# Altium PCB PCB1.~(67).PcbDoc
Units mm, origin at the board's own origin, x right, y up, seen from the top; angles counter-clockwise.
Board outline 68 x 68 mm, 2 copper layers (Top Layer, Bottom Layer); 37 components, 24 nets, 122 pads, 15 vias.
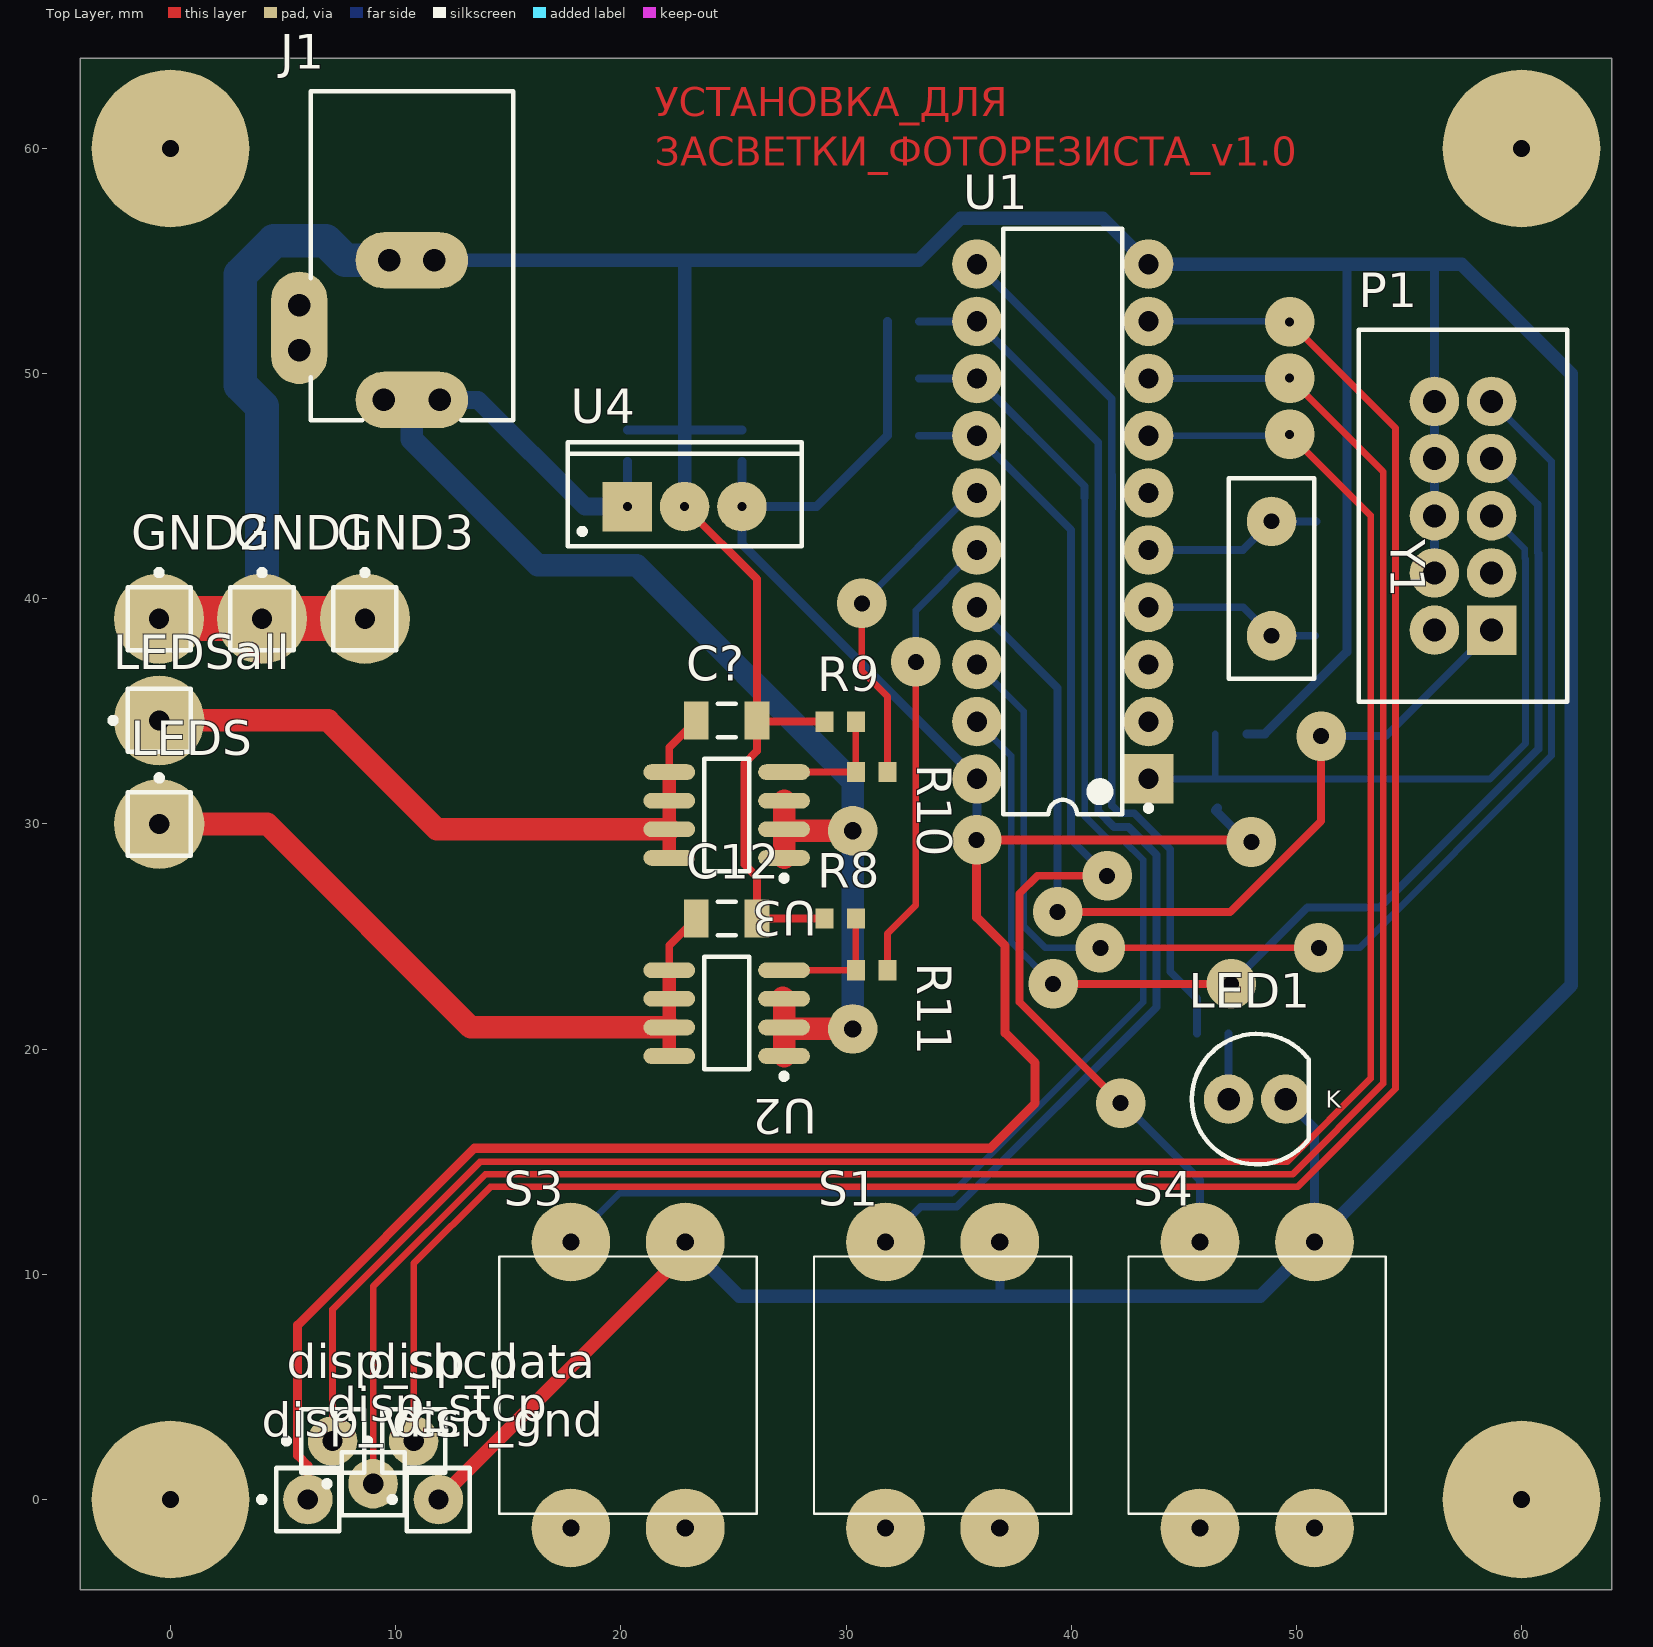
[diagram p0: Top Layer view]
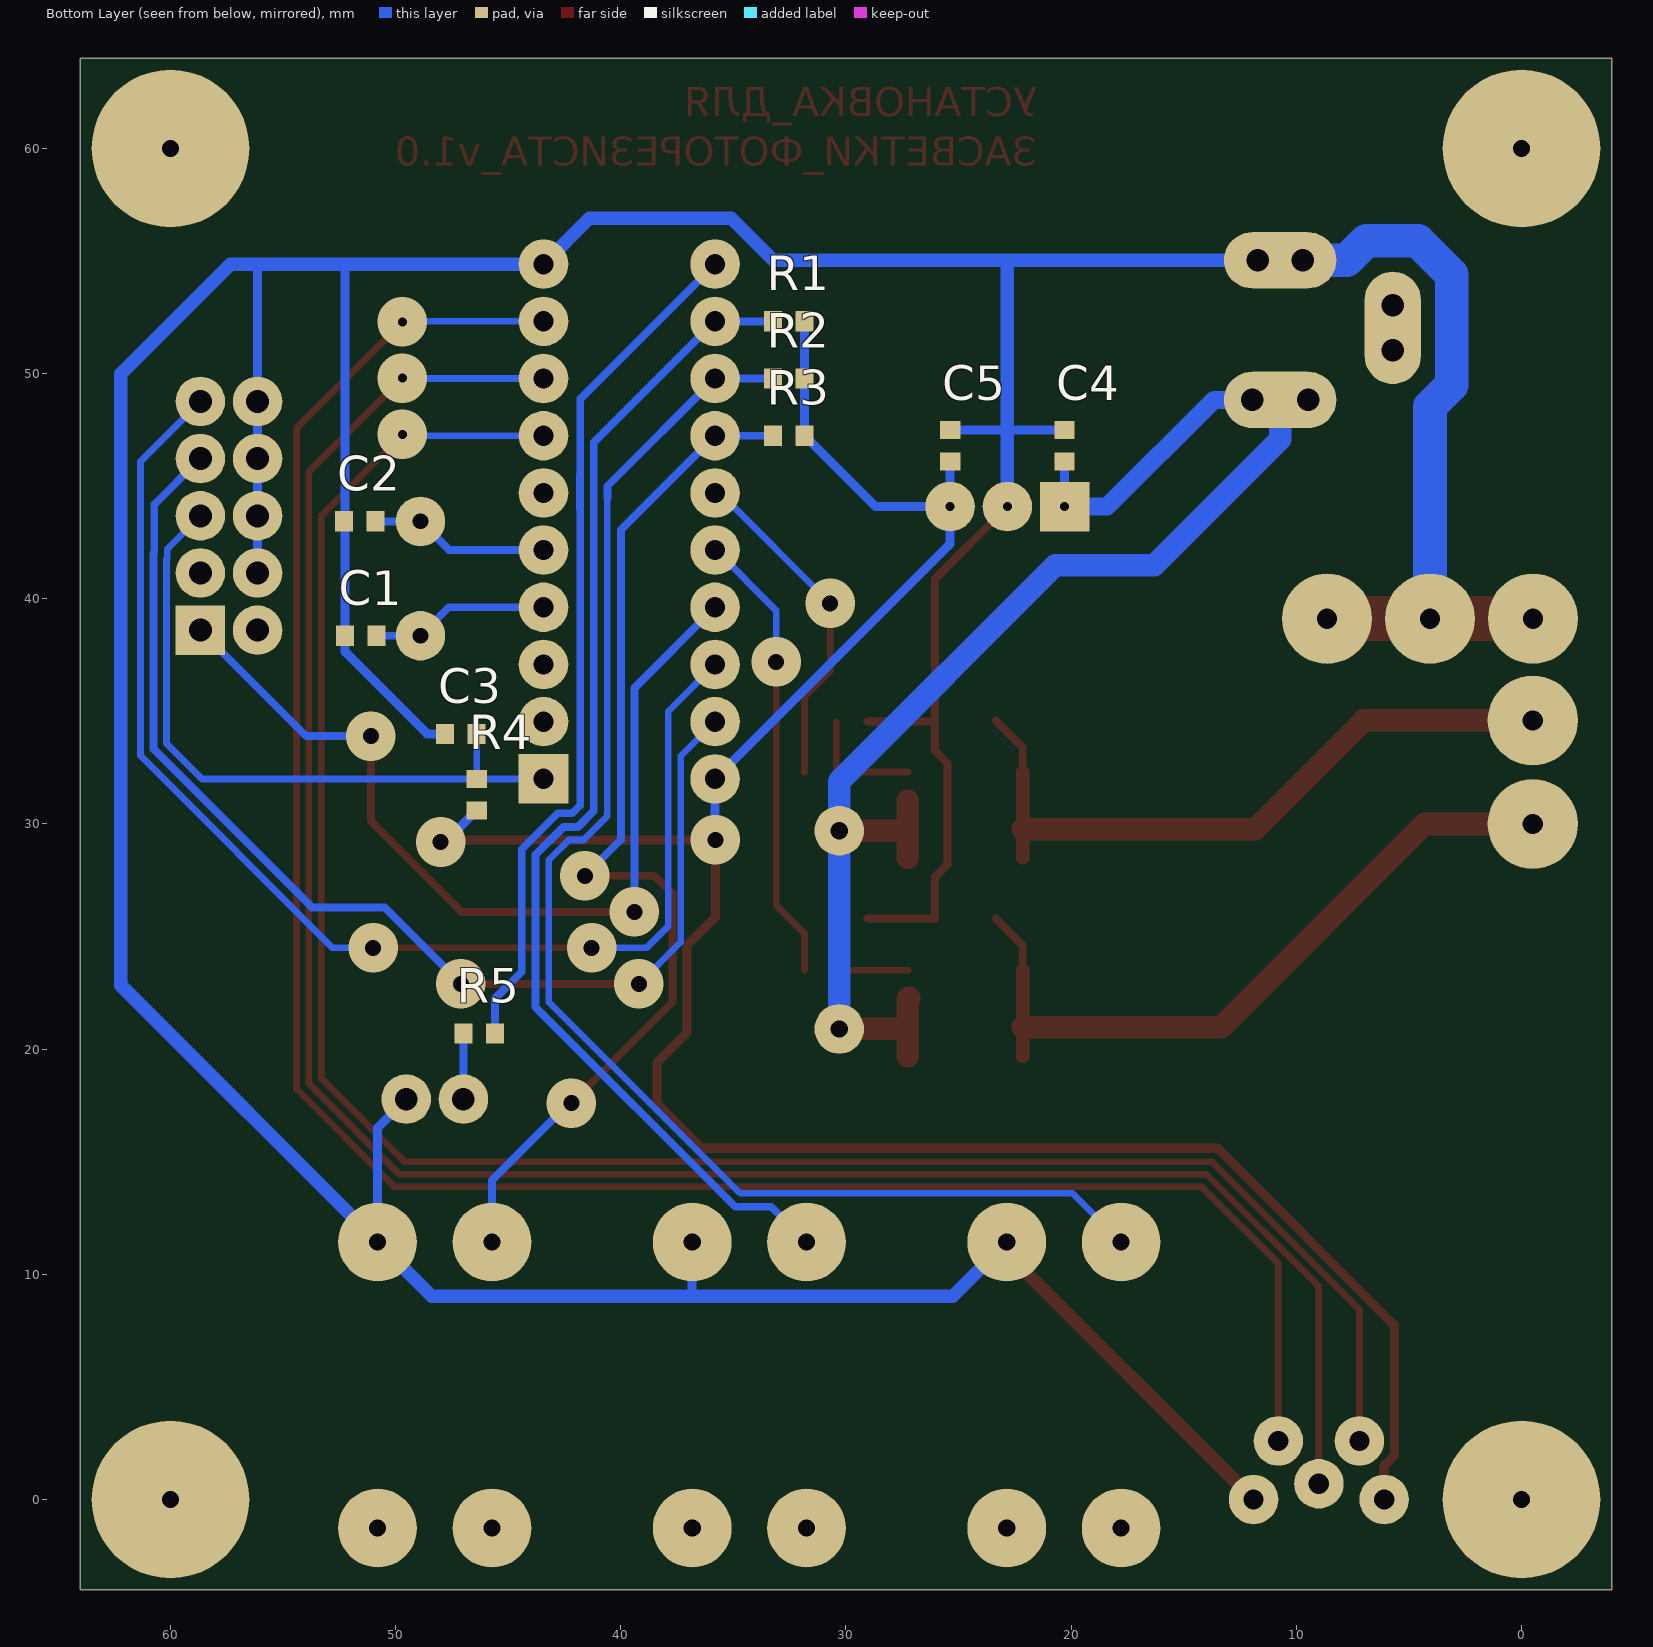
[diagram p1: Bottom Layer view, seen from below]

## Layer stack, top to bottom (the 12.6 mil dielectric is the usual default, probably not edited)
Top Solder: solder mask 0.0102, Solder Resist, Dk 3.5
Top Layer: signal copper 0.0356
Dielectric 1: dielectric 0.32, FR-4, Dk 4.8
Bottom Layer: signal copper 0.0356
Bottom Solder: solder mask 0.0102, Solder Resist, Dk 3.5

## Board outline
-4,-4 64,-4 64,64 -4,64

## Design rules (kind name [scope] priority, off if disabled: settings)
Clearance Clearance_U1_1 [InComponent('U1') vs IsRegion] p1: gap=0.254
Clearance Clearance_U1 [InComponent('U1') vs OnLayer('Top Layer')] p2: gap=0.178
Clearance [All] p3: gap=0.254
MinimumSolderMaskSliver [All] p1 off: minsoldermaskwidth=0.254
PasteMaskExpansion [All] p1 off: expansion=0
PolygonConnect [All] p1: connectstyle=Relief reliefconductorwidth=0.254 reliefentries=4 polygonreliefangle="90 Angle" airgapwidth=0.254
RoutingVias [All] p1: holewidth=0.711 width=1.27 viastyle="Through Hole" minholewidth=0.254 minwidth=0.508 maxholewidth=0.762 maxwidth=5
SolderMaskExpansion [All] p1 off: expansion=0.102
Width [All] p1: maxlimit=5 minlimit=0.3 preferedwidth=0.35
28 further rules are at their usual default settings.

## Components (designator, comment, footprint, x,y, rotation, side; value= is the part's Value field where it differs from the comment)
C1 "Cap Semi" CAPC1608L 51.54,38.36 r180 bottom
C2 "Cap Semi" CAPC1608L 51.6,43.44 r180 bottom
C3 "Cap Semi" CAPC1608L 47.1,34 r0 bottom
C4 "Cap Semi" CAPC1608L 20.3,46.8 r270 bottom
C5 "Cap Semi" CAPC1608L 25.375,46.8 r270 bottom
C12 "Cap Semi" CAPC3216L 24.7,25.8 r0 top
C? "Cap Semi" CAPC3216L 24.7,34.6 r0 top
disp_data "uleds_all" PIN1#1 10.8,2.6 r90 top
disp_gnd "uleds_all" PIN1#1 11.9,0 r90 top
disp_shcp "uleds_all" PIN1#1 7.2,2.6 r90 top
disp_stcp "uleds_all" PIN1#1 9,0.7 r90 top
disp_vcc "uleds_all" PIN1#1 6.1,0 r90 top
GND1 "GNDout" PIN1#2 4.064,39.116 r0 top
GND2 "GNDout" PIN1#2 -0.508,39.116 r0 top
GND3 "GNDout" PIN1#2 8.636,39.116 r0 top
J1 "PWR2.5" PCBComponent_1 10.719,54.915 r270 top
LED1 "151051YS04000" "Type 5mm" 48.26,17.78 r0 top
LEDS "uleds" PIN1#2 -0.5,30 r0 top
LEDSall "uleds_all" PIN1#2 -0.5,34.6 r90 top
P1 "ZSS-105-01-F-D-450" SMTC-ZSS-105-01-X-D-450 58.674,38.608 r90 top
R1 "Res3" CAPC1608L 32.537,52.324 r0 bottom
R2 "Res3" CAPC1608L 32.537,49.784 r0 bottom
R3 "Res3" CAPC1608L 32.537,47.244 r0 bottom
R4 "Res3" CAPC1608L 46.4,31.304 r90 bottom
R5 "Res3" CAPC1608L 46.29,20.701 r0 bottom
R8 "Res3" CAPC1608L 29.737,25.8 r0 top
R9 "Res3" CAPC1608L 29.737,34.544 r0 top
R10 "Res3" CAPC1608L 31.137,32.305 r0 top
R11 "Res3" CAPC1608L 31.137,23.505 r0 top
S1 "START_min" key 34.29,5.08 r180 top
S3 "START_all" key 20.32,5.08 r180 top
S4 "PAUSE" key 48.26,5.08 r180 top
U1 "ATtiny2313V-10PU" 20P3 39.624,43.434 r180 top
U2 "IRF7452PBF" SO-8_M 24.7,21.6 r180 top
U3 "IRF7452PBF" SO-8_M 24.7,30.4 r180 top
U4 "MC78M05CTG" TO220 22.835,44.094 r0 top
Y1 "16MHz" "PCBComponent_1 - duplicate" 48.9,40.9 r0 top

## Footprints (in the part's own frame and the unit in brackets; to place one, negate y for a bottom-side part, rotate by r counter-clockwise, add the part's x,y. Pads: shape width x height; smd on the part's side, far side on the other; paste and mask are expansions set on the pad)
20P3 [mm] "DIP, 20-Pin, Row Spacing 7.62 mm, Pitch 2.54 mm"
  rect 2.2x2.2 hole 0.9: 1(-3.81,11.43)
  round 2.2 hole 0.9: 2(-3.81,8.89) 3(-3.81,6.35) 4(-3.81,3.81) 5(-3.81,1.27) 6(-3.81,-1.27) 7(-3.81,-3.81) 8(-3.81,-6.35) 9(-3.81,-8.89) 10(-3.81,-11.43) 11(3.81,-11.43) 12(3.81,-8.89) 13(3.81,-6.35) 14(3.81,-3.81) 15(3.81,-1.27) 16(3.81,1.27) 17(3.81,3.81) 18(3.81,6.35) 19(3.81,8.89) 20(3.81,11.43)
  silkscreen extent -3.94,-13 2.65,13, body extent -3.6,-12.95 3.6,12.95, height 5.08
CAPC1608L [mm] "Chip Capacitor, Body 1.6x0.8mm, IPC High Density"
  rect 0.8x0.9 smd: 1(-0.7,0) 2(0.7,0)
  body extent -0.87,-0.48 0.87,0.48, height 1.3
CAPC3216L [mm] "Chip Capacitor, Body 3.2x1.6mm, IPC High Density"
  rect 1.1x1.7 smd: 1(-1.35,0) 2(1.35,0)
  silkscreen extent -0.4,-0.75 0.4,0.75, body extent -1.7,-0.9 1.7,0.9, height 1.3
key [mm]
  round 3.5 hole 0.762: 1(2.54,-6.35) 2(-2.54,-6.35) 3(-2.54,6.35) 4(2.54,6.35)
  silkscreen extent -5.72,-5.72 5.72,5.72, body extent -6.35,-6.35 6.35,6.35, height 11.94
PCBComponent_1 [mm]
  oval 2.5x5 all layers, no hole: 1(6.08,0) 2(-0.12,0)
  round 1.5 hole 1: 1A(6.08,-1.25) 1B(6.08,1.25) 2A(-0.12,-1) 2B(-0.12,1) 3A(1.88,-5) 3B(3.88,-5)
  oval 5x2.5 all layers, no hole: 3(2.88,-5)
  silkscreen extent -7.62,-4.5 6.98,4.5, body extent -7.87,-5.6 6.83,5.6, height 11
"PCBComponent_1 - duplicate" [mm]
  round 2.2 hole 0.7: 1(0,-2.54) 2(0,2.54)
  silkscreen extent -1.91,-4.44 1.91,4.44, body extent -2.33,-5.67 2.32,5.68, height 3.6
PIN1#1 [mm] "Connector; Plug"
  round 2.2 hole 0.9: 1(0,0)
  silkscreen extent -1.4,-1.4 1.4,2.17
PIN1#2 [mm] "Connector; Plug"
  round 4 hole 0.9: 1(0,0)
  silkscreen extent -1.4,-1.4 1.4,2.17
SMTC-ZSS-105-01-X-D-450 [mm] "Shrouded .025\" SQ Post Header, 2x5 Pins, Vertical, 2.54mm Pitch, Male"
  rect 2.2x2.2 hole 1.02: 1(0,0)
  round 2.2 hole 1.02: 2(0,2.54) 3(2.54,0) 4(2.54,2.54) 5(5.08,0) 6(5.08,2.54) 7(7.62,0) 8(7.62,2.54) 9(10.16,0) 10(10.16,2.54)
  silkscreen extent -3.18,-3.36 13.33,5.9, body extent -3.17,-3.57 13.34,5.91, height 11.43
SO-8_M [mm] "SOIC, 8-Leads, Body 4.9x3.9mm, Pitch 1.27mm, IPC Low Density"
  oval 2.3x0.7 smd: 1(-2.55,1.905) 2(-2.55,0.635) 3(-2.55,-0.635) 4(-2.55,-1.905) 5(2.55,-1.905) 6(2.55,-0.635) 7(2.55,0.635) 8(2.55,1.905)
  silkscreen extent -2.68,-2.5 1,2.93, body extent -2,-2.5 2,2.5, height 1.75
TO220 [mm] "TO, Thru-Hole, Vertical, Heatsink Mounted; 3 In-Line Leads; Pitch 2.54 mm"
  rect 2.2x2.2 hole 0.4: 1(-2.54,0)
  round 2.2 hole 0.4: 2(0,0) 3(2.54,0)
  silkscreen extent -5.2,-1.75 5.2,2.85, body extent -5.25,-1.8 5.25,2.9, height 19.7
"Type 5mm" [mm] "THT, LED-5mm, 2pin- Body 5.8mm"
  round 2.2 hole 1: 1(1.27,0) 2(-1.27,0)
  silkscreen extent -2.9,-2.9 2.29,2.9, body extent -2.9,-2.9 2.5,2.9, height 11.7

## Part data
C1 C2 C3 C4 C5 C12 C?: "Capacitor (Semiconductor SIM Model)"
disp_data disp_gnd disp_shcp disp_stcp disp_vcc GND1 GND2 GND3 LEDS LEDSall: library part Plug, "Plug"
J1: "Low Voltage Power Supply Connector"
LED1: library part CMP-1488-00010-1, "THT LED round mono-color color lens, WL-TMRW, Yellow"
P1: library part CMP-1024-00461-1
R1 R2 R3 R4 R5 R8 R9 R10 R11: "Resistor"
S1 S3 S4: library part SW-DPST, "Double-Pole, Single-Throw Switch"
U1: library part CMP-0093-00017-1, "Low Power tinyAVR® 8-Bit Microcontroller, 2K Flash Memory, 10MHz, Industrial Temperature, 20-Lead PDIP, Pb-Free"
U4: library part CMP-0244-00483-1, "Positive Voltage Regulator, 5V, 3-Pin TO-220"
Y1: library part XTAL, "Crystal Oscillator"

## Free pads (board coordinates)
  round 7 hole 0.762: 4(0,0) 5(60,0) 7(60,60) 8(0,60)
  round 2.2 hole 0.762: 9(30.3,20.9) 9(30.3,29.7)

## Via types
v1: diameter 2.2, hole 0.711, Top Layer to Bottom Layer, 12 vias
v2: diameter 2.2, hole 0.4, Top Layer to Bottom Layer, 3 vias

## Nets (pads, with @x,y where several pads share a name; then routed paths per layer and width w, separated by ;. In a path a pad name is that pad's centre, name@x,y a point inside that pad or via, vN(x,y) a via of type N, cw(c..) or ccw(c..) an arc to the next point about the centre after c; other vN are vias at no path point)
+24V: C4.2 J1.1 J1.1A J1.1B pad.9 U2.1 U2.2 U2.3 U3.1 U3.2 U3.3 U4.1 | length 63.3
  Top Layer w1: U2.3@27.2,22.285 U2.3 U2.2 U2.1 ; U3.1 U3.2 U3.3 ; U2.2@27.315,20.9 pad.9@30.3,20.9 ; U3.2@27.315,29.7 pad.9@30.3,29.7
  Bottom Layer w0.4: U4.1@20.3,44.1 C4.2
  Bottom Layer w0.8: J1.1B 13.665,48.835 18.406,44.094 U4.1
  Bottom Layer w1: J1.1B J1.1 10.719,47.081 16.3,41.5 20.7,41.5 30.3,31.9 30.3,29.7 pad.9@30.3,20.9
BUT_PAUSE: R3.2 S4.1 U1.14 | length 47.6
  Top Layer w0.35: v1(41.6,27.7) 38.5,27.7 37.7,26.9 37.7,22.1 v1(42.2,17.6)
  Bottom Layer w0.35: R3.2 U1.14 40,43.058 40,29.3 v1(41.6,27.7) ; v1(42.2,17.6) 42.3,17.6 45.72,14.18 S4.1
BUT_START: R1.2 S1.1 U1.12 | length 53.1
  Bottom Layer w0.35: S1.1 33.32,13 34.919,13 43.796,21.877 43.796,28.623 42.548,29.871 41.906,29.871 41.2,30.577 41.2,44.246 41.204,44.25 41.204,45.248 41.2,45.252 41.2,46.938 U1.12 R1.2
BUT_STARTALL: R2.2 S3.1 U1.13 | length 63.5
  Bottom Layer w0.3: S3.1 19.95,13.6 34.7,13.6 43.2,22.1 43.2,28.4 42.308,29.292 41.666,29.292 40.6,30.358 40.6,44.5
  Bottom Layer w0.35: R2.2 U1.13 40.6,44.998 40.6,44.5
DISP_DATA: disp_data.1 U1.9 | length 97
  Top Layer w0.3: disp_data.1 10.8,10.479 14.209,13.888 50.055,13.888 54.408,18.241 54.408,47.592 v2(49.7,52.3)
  Bottom Layer w0.3: U1.9 49.676,52.324 v2(49.7,52.3)
DISP_SHCP: disp_shcp.1 U1.7 | length 92.6
  Top Layer w0.3: disp_shcp.1 7.2,8.446 13.75,14.996 49.596,14.996 53.3,18.7 53.3,43.7 v2(49.7,47.3)
  Bottom Layer w0.3: U1.7 49.644,47.244 v2(49.7,47.3)
DISP_STCP: disp_stcp.1 U1.8 | length 96.7
  Top Layer w0.3: disp_stcp.1 9,9.462 13.98,14.442 49.825,14.442 53.854,18.471 53.854,45.646 v2(49.7,49.8)
  Bottom Layer w0.3: U1.8 49.684,49.784 v2(49.7,49.8)
GND: C1.1 C2.1 C3.2 C4.1 C5.1 C12.2 C?.2 disp_gnd.1 GND1.1 GND2.1 GND3.1 J1.2 J1.2A J1.2B LED1.1 P1.4 P1.6 P1.8 P1.10 R8.1 R9.1 S1.2 S3.2 S4.2 U1.10 U4.2 | length 265.7
  Top Layer w0.35: U4.2 26.05,40.879 C?.2 26.05,33.25 25.5,32.7 25.5,28.2 26.05,27.65 C12.2 R8.1 ; C?.2@26.106,34.544 R9.1
  Top Layer w0.6: disp_gnd.1 22.86,10.96 S3.2
  Top Layer w2: GND2.1 GND1.1 GND3.1
  Bottom Layer w0.4: C4.1 22.835,47.5 C5.1 ; 36.83,9.03 S1.2 ; C3.2 48.6,34 52.24,37.64 52.24,54.864 ; LED1.1 50.8,16.51 S4.2 ; P1.4 P1.6 P1.8 P1.10 56.134,54.7
  Bottom Layer w0.6: J1.2B 33.235,55.035 35.1,56.9 41.398,56.9 U1.10 57.336,54.864 62.2,50 62.2,22.83 S4.2 48.4,9.03 36.83,9.03 25.26,9.03 S3.2 ; U4.2 22.835,55.035
  Bottom Layer w0.8: J1.2A J1.2 J1.2B
  Bottom Layer w1.5: GND1.1 4.064,48.536 3.1,49.5 3.1,54.4 4.6,55.9 6.9,55.9 7.765,55.035 J1.2A
MISO: P1.9 U1.18 | length 56.7
  Top Layer w0.3: v1(41.3,24.5) 41.304,24.504 50.996,24.504 v1(51,24.5)
  Bottom Layer w0.3: U1.18 37.892,35.006 37.892,25.473 38.865,24.5 v1(41.3,24.5) ; v1(51,24.5) 52.8,24.5 61.336,33.036 61.336,46.106 P1.9
MOSI: P1.1 U1.17 | length 41.7
  Top Layer w0.35: v1(39.396,26.096) 47.058,26.096 51.1,30.138 v1(51.1,33.9)
  Bottom Layer w0.35: U1.17 39.396,36.042 v1(39.396,26.096) ; v1(51.1,33.9) 53.966,33.9 P1.1
NetC1_2: C1.2 U1.4 Y1.1 | length 7.9
  Bottom Layer w0.35: U1.4 47.636,39.624 Y1.1 C1.2
NetC2_2: C2.2 U1.5 Y1.2 | length 8
  Bottom Layer w0.35: U1.5 47.624,42.164 Y1.2 C2.2
NetC12_1: C12.1 LEDS.1 U2.5 U2.6 U2.7 U2.8 | length 33.6
  Top Layer w0.35: U2.5 22.15,24.6 C12.1
  Top Layer w0.6: U2.8 U2.7 U2.6 U2.5
  Top Layer w1: LEDS.1@-0.5,31.4 0.9,30 4.3,30 13.335,20.965 U2.7
NetC?_1: C?.1 LEDSall.1 U3.5 U3.6 U3.7 U3.8 | length 31.4
  Top Layer w0.35: U3.5 22.15,33.4 C?.1
  Top Layer w0.6: U3.8 U3.7 U3.6 U3.5
  Top Layer w1: LEDSall.1@-0.508,34.9 -0.208,34.6 7,34.6 11.835,29.765 U3.7
NetJ1_3: J1.3 J1.3A J1.3B
NetLED1_2: LED1.2 R5.2 | length 2.9
  Bottom Layer w0.35: LED1.2 R5.2
NetR5_1: R5.1 U1.11 | length 38.6
  Bottom Layer w0.35: U1.11 41.804,48.874 41.804,45.502 41.808,45.498 41.808,44 41.804,43.996 41.804,30.827 42.156,30.475 42.798,30.475 44.4,28.873 44.4,23.438 45.59,22.248 R5.1
NetR8_2: R8.2 R11.1 U2.4 | length 5.3
  Top Layer w0.3: U2.4 R11.1 R8.2@30.437,25.65
NetR9_2: R9.2 R10.1 U3.4 | length 5.4
  Top Layer w0.3: U3.4 R10.1 R9.2
RES: C3.1 P1.5 R4.2 U1.1 | length 30.1
  Bottom Layer w0.3: U1.1 R4.2 ; C3.1 R4.2 ; P1.5 60.142,42.22 60.142,41.807 60.178,41.771 60.178,33.578 58.604,32.004 R4.2
SCK: P1.7 U1.19 | length 52.7
  Top Layer w0.35: v1(39.2,22.9) v1(47.1,22.9)
  Bottom Layer w0.3: U1.19 37.338,33.02 37.338,24.762 v1(39.2,22.9)
  Bottom Layer w0.35: v1(47.1,22.9) 50.5,26.3 53.719,26.3 60.757,33.338 60.757,40.115 60.757,40.285 60.757,42.011 60.721,42.047 60.721,44.181 P1.7
ULEDS: R11.2 U1.16 | length 20.3
  Top Layer w0.3: R11.2 31.837,25.137 33.1,26.4 v1(33.1,37.2)
  Bottom Layer w0.3: v1(33.1,37.2) 33.1,39.488 U1.16@35.776,42.164
ULEDSALL: R10.2 U1.15 | length 15.1
  Top Layer w0.3: v1(30.7,39.8) 30.7,36.8 31.837,35.663 R10.2
  Bottom Layer w0.3: v1(30.7,39.8) 35.604,44.704 U1.15
VCC: C5.2 disp_vcc.1 R1.1 R2.1 R3.1 R4.1 U1.20 U4.3 | length 106.5
  Top Layer w0.4: disp_vcc.1 6.1,1.502 5.646,1.956 5.646,7.746 13.5,15.6 36.4,15.6 38.404,17.604 38.404,19.396 37.071,20.729 37.071,24.583 35.8,25.854 v1(35.8,29.3) 47.9,29.3 v1(48,29.2)
  Bottom Layer w0.4: C5.2 U4.3 ; R1.1 R2.1 R3.1 28.688,44.094 U4.3 ; v1(35.8,29.3) 35.528,29.3 35.814,29.586 U1.20 25.375,42.443 U4.3 ; R4.1@46.498,30.702 R4.1 47.804,29.2 v1(48,29.2)
pads on no net: P1.2 P1.3 S1.3 S1.4 S3.3 S3.4 S4.3 S4.4 U1.2 U1.3 U1.6

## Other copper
Top Layer:
  text "УСТАНОВКА_ДЛЯ / ЗАСВЕТКИ_ФОТОРЕЗИСТА_v1.0" at 21.5,58.8 h2.2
